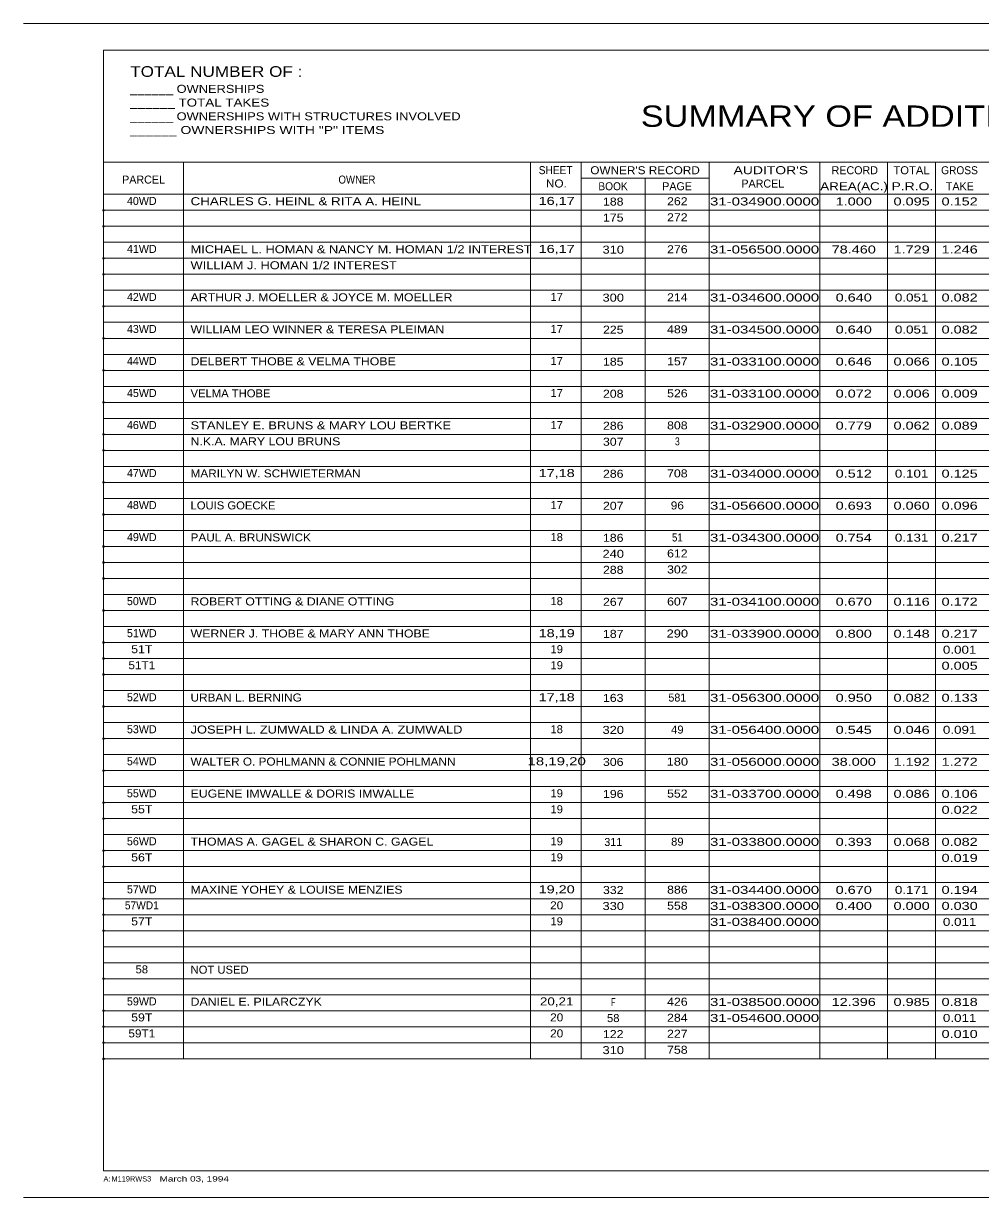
# Model space of a CAD drawing. Extents: x -1 to 34.5, y 0 to 22.
# Drawn here: x -1 to 16.94, y 0 to 22 of the extents above; entities that cross this region are included whole.
import ezdxf
from ezdxf.enums import TextEntityAlignment as Align

# ---------------------------------------------------------------- set-up
doc = ezdxf.new("R2010")
doc.units = 0
doc.header["$LTSCALE"] = 0.06
doc.header["$PDMODE"] = 32
doc.header["$PDSIZE"] = 0.03
doc.layers.add('1', color=7, linetype='Continuous', lineweight=13)

msp = doc.modelspace()

# ---------------------------------------------------------------- linework, layer by layer
at = {"layer": '1'}
for p, q in [((-1, 22), (34.5, 22)), ((0.5, 21.5), (34, 21.5)), ((0.5, 0.5), (0.5, 21.5)), ((0.5, 19.4), (34, 19.4)), ((2, 2.6), (2, 19.4)), ((8.5, 2.6), (8.5, 19.4)), ((9.45025, 2.6), (9.45025, 19.4)), ((11.85025, 2.6), (11.85025, 19.4)), ((13.92625, 2.6), (13.92625, 19.4)), ((15.19617, 2.6), (15.19617, 19.4)), ((16.09617, 2.6), (16.09617, 19.4)), ((9.45025, 19.1), (11.85025, 19.1)), ((10.65025, 2.6), (10.65025, 19.1)), ((0.5, 18.8), (34, 18.8)), ((0.5, 18.5), (34, 18.5)), ((0.5, 18.2), (34, 18.2)), ((0.5, 17.9), (34, 17.9)), ((0.5, 17.6), (34, 17.6)), ((0.5, 17.3), (34, 17.3)), ((0.5, 17), (34, 17)), ((0.5, 16.7), (34, 16.7)), ((0.5, 16.4), (34, 16.4)), ((0.5, 16.1), (34, 16.1)), ((0.5, 15.8), (34, 15.8)), ((0.5, 15.5), (34, 15.5)), ((0.5, 15.2), (34, 15.2)), ((0.5, 14.9), (34, 14.9)), ((0.5, 14.6), (34, 14.6)), ((0.5, 14.3), (34, 14.3)), ((0.5, 14), (34, 14)), ((0.5, 13.7), (34, 13.7)), ((0.5, 13.4), (34, 13.4)), ((0.5, 13.1), (34, 13.1)), ((0.5, 12.8), (34, 12.8)), ((0.5, 12.5), (34, 12.5)), ((0.5, 12.2), (34, 12.2)), ((0.5, 11.9), (34, 11.9)), ((0.5, 11.6), (34, 11.6)), ((0.5, 11.3), (34, 11.3)), ((0.5, 11), (34, 11)), ((0.5, 10.7), (34, 10.7)), ((0.5, 10.4), (34, 10.4)), ((0.5, 10.1), (34, 10.1)), ((0.5, 9.8), (34, 9.8)), ((0.5, 9.5), (34, 9.5)), ((0.5, 9.2), (34, 9.2)), ((0.5, 8.9), (34, 8.9)), ((0.5, 8.6), (34, 8.6)), ((0.5, 8.3), (34, 8.3)), ((0.5, 8), (34, 8)), ((0.5, 7.7), (34, 7.7)), ((0.5, 7.4), (34, 7.4)), ((0.5, 7.1), (34, 7.1)), ((0.5, 6.8), (34, 6.8)), ((0.5, 6.5), (34, 6.5)), ((0.5, 6.2), (34, 6.2)), ((0.5, 5.9), (34, 5.9)), ((0.5, 5.6), (34, 5.6)), ((0.5, 5.3), (34, 5.3)), ((0.5, 5), (34, 5)), ((0.5, 4.7), (34, 4.7)), ((0.5, 4.4), (34, 4.4)), ((0.5, 4.1), (34, 4.1)), ((0.5, 3.8), (34, 3.8)), ((0.5, 3.5), (34, 3.5)), ((0.5, 3.2), (34, 3.2)), ((0.5, 2.9), (34, 2.9)), ((0.5, 2.6), (34, 2.6)), ((0.5, 2.6), (12.5, 2.6)), ((-1, 0), (34.5, 0))]:
    msp.add_line(p, q, dxfattribs=at)
msp.add_lwpolyline([(34, 21.5), (34, 0.5), (0.5, 0.5)], dxfattribs=at)
for p in [(0.5, 18.5), (0.5, 18.2), (0.5, 17.6), (0.5, 17.3), (0.5, 16.7), (0.5, 16.1), (0.5, 15.5), (0.5, 14.9), (0.5, 14.3), (0.5, 14), (0.5, 13.4), (0.5, 12.8), (0.5, 12.2), (0.5, 11.9), (0.5, 11.6), (0.5, 11), (0.5, 10.4), (0.5, 10.1), (0.5, 9.8), (0.5, 9.2), (0.5, 8.6), (0.5, 8), (0.5, 7.4), (0.5, 7.1), (0.5, 6.5), (0.5, 6.2), (0.5, 5.6), (0.5, 5.3), (0.5, 5), (0.5, 4.1), (0.5, 3.5), (0.5, 3.2), (0.5, 2.9), (0.5, 2.6)]:
    msp.add_point(p, dxfattribs=at)

# ---------------------------------------------------------------- texts
for s, height, width, p in [('TOTAL NUMBER OF :', 0.2, 1.2, (1, 21)), ('______ OWNERSHIPS', 0.15, 1.2, (1, 20.7)), ('______ TOTAL TAKES', 0.15, 1.25, (1, 20.44283)), ('______ OWNERSHIPS WITH STRUCTURES INVOLVED', 0.15, 1.2, (1, 20.18575)), ('______ OWNERSHIPS WITH "P" ITEMS', 0.15, 1.3, (1, 19.92858)), ("AUDITOR'S ", 0.15, 1.3, (12.30883, 19.176)), (' NO.', 0.15, 1.1, (8.73083, 18.92683)), ('CHARLES G. HEINL & RITA A. HEINL', 0.15, 1.25, (2.13167, 18.59433)), ('MICHAEL L. HOMAN & NANCY M. HOMAN 1/2 INTEREST', 0.15, 1.2, (2.13167, 17.69433)), ('WILLIAM J. HOMAN 1/2 INTEREST', 0.15, 1.2, (2.13167, 17.39433)), ('ARTHUR J. MOELLER & JOYCE M. MOELLER', 0.15, 1.15, (2.13167, 16.79433)), ('WILLIAM LEO WINNER & TERESA PLEIMAN', 0.15, 1.15, (2.13167, 16.19433)), ('DELBERT THOBE & VELMA THOBE', 0.15, 1.15, (2.13167, 15.59433)), ('VELMA THOBE', 0.15, 1.05, (2.13167, 14.99433)), ('STANLEY E. BRUNS & MARY LOU BERTKE', 0.15, 1.2, (2.13167, 14.39433)), ('N.K.A. MARY LOU BRUNS', 0.15, 1.15, (2.13167, 14.09433)), ('MARILYN W. SCHWIETERMAN', 0.15, 1.1, (2.13167, 13.49433)), ('LOUIS GOECKE', 0.15, 1.05, (2.13167, 12.89433)), ('PAUL A. BRUNSWICK', 0.15, 1.1, (2.13167, 12.29433)), ('ROBERT OTTING & DIANE OTTING', 0.15, 1.15, (2.13167, 11.09433)), ('WERNER J. THOBE & MARY ANN THOBE', 0.15, 1.15, (2.13167, 10.49433)), ('URBAN L. BERNING', 0.15, 1.1, (2.13167, 9.29433)), ('JOSEPH L. ZUMWALD & LINDA A. ZUMWALD', 0.15, 1.2, (2.13167, 8.69433)), ('WALTER O. POHLMANN & CONNIE POHLMANN', 0.15, 1.1, (2.13167, 8.09433)), ('EUGENE IMWALLE & DORIS IMWALLE', 0.15, 1.15, (2.13167, 7.49433)), ('THOMAS A. GAGEL & SHARON C. GAGEL', 0.15, 1.15, (2.13167, 6.59433)), ('MAXINE YOHEY & LOUISE MENZIES', 0.15, 1.15, (2.13167, 5.69433)), ('NOT USED', 0.15, 1.05, (2.13167, 4.19433)), ('DANIEL E. PILARCZYK', 0.15, 1.15, (2.13167, 3.59433)), ('March 03, 1994', 0.1, 1.4, (1.55, 0.3))]:
    msp.add_text(s, height=height, dxfattribs=dict(at, width=width)).set_placement(p)
for s, height, width, p in [('SUMMARY OF ADDITIONAL RIGHT-OF-WAY', 0.4, 1.2, (17.2385, 20.06342)), ('OWNER', 0.15, 0.9, (5.25004, 19)), ('SHEET', 0.15, 0.95, (8.97467, 19.17683)), ("OWNER'S RECORD", 0.15, 1.1, (10.65025, 19.175)), ('TOTAL', 0.15, 1.05, (15.64387, 19.175)), ('GROSS', 0.15, 0.95, (16.54367, 19.175)), ('BOOK', 0.15, 0.95, (10.05029, 18.875)), ('AREA(AC.)', 0.15, 1.25, (14.56738, 18.875)), ('P.R.O.', 0.15, 1.3, (15.66092, 18.875)), ('16,17', 0.15, 1.35, (8.99346, 18.60025)), ('188', 0.15, 1.15, (10.05379, 18.5875)), ('262', 0.15, 1.15, (11.25512, 18.59383)), ('31-034900.0000', 0.15, 1.4, (12.89025, 18.59)), ('1.000', 0.15, 1.35, (14.56129, 18.59)), ('0.095', 0.15, 1.35, (15.64612, 18.59)), ('0.152', 0.15, 1.35, (16.54612, 18.59)), ('175', 0.15, 1.15, (10.05379, 18.2875)), ('272', 0.15, 1.15, (11.25512, 18.29383)), ('16,17', 0.15, 1.35, (8.99346, 17.70025)), ('310', 0.15, 1.2, (10.05387, 17.6875)), ('276', 0.15, 1.15, (11.25521, 17.69383)), ('31-056500.0000', 0.15, 1.4, (12.89025, 17.69)), ('78.460', 0.15, 1.35, (14.56121, 17.69)), ('1.729', 0.15, 1.35, (15.64612, 17.69)), ('1.246', 0.15, 1.35, (16.54621, 17.69)), ('17', 0.15, 1.05, (8.9935, 16.80025)), ('214', 0.15, 1.15, (11.25512, 16.79383)), ('31-034600.0000', 0.15, 1.4, (12.89025, 16.79)), ('0.640', 0.15, 1.35, (14.56129, 16.79)), ('0.051', 0.15, 1.25, (15.64617, 16.79)), ('0.082', 0.15, 1.35, (16.54612, 16.79)), ('300', 0.15, 1.2, (10.05387, 16.7875)), ('17', 0.15, 1.05, (8.9935, 16.20025)), ('225', 0.15, 1.15, (10.05379, 16.1875)), ('489', 0.15, 1.15, (11.25512, 16.19383)), ('31-034500.0000', 0.15, 1.4, (12.89025, 16.19)), ('0.640', 0.15, 1.35, (14.56129, 16.19)), ('0.051', 0.15, 1.25, (15.64617, 16.19)), ('0.082', 0.15, 1.35, (16.54612, 16.19)), ('17', 0.15, 1.05, (8.9935, 15.60025)), ('185', 0.15, 1.15, (10.05379, 15.5875)), ('157', 0.15, 1.15, (11.25512, 15.59383)), ('31-033100.0000', 0.15, 1.4, (12.89025, 15.59)), ('0.646', 0.15, 1.35, (14.56129, 15.59)), ('0.066', 0.15, 1.35, (15.64621, 15.59)), ('0.105', 0.15, 1.35, (16.54612, 15.59)), ('17', 0.15, 1.05, (8.9935, 15.00025)), ('208', 0.15, 1.15, (10.05379, 14.9875)), ('526', 0.15, 1.15, (11.25521, 14.99383)), ('31-033100.0000', 0.15, 1.4, (12.89025, 14.99)), ('0.072', 0.15, 1.35, (14.56121, 14.99)), ('0.006', 0.15, 1.35, (15.64621, 14.99)), ('0.009', 0.15, 1.35, (16.54612, 14.99)), ('17', 0.15, 1.05, (8.9935, 14.40025)), ('286', 0.15, 1.15, (10.05387, 14.3875)), ('808', 0.15, 1.15, (11.25512, 14.39383)), ('31-032900.0000', 0.15, 1.4, (12.89025, 14.39)), ('0.779', 0.15, 1.35, (14.56121, 14.39)), ('0.062', 0.15, 1.35, (15.64612, 14.39)), ('0.089', 0.15, 1.35, (16.54612, 14.39)), ('307', 0.15, 1.15, (10.05379, 14.0875)), ('3', 0.15, 0.8, (11.25517, 14.09383)), ('17,18', 0.15, 1.35, (8.99346, 13.50025)), ('708', 0.15, 1.15, (11.25512, 13.49383)), ('31-034000.0000', 0.15, 1.4, (12.89025, 13.49)), ('0.512', 0.15, 1.35, (14.56121, 13.49)), ('0.101', 0.15, 1.25, (15.64617, 13.49)), ('0.125', 0.15, 1.35, (16.54612, 13.49)), ('286', 0.15, 1.15, (10.05387, 13.4875)), ('17', 0.15, 1.05, (8.9935, 12.90025)), ('207', 0.15, 1.15, (10.05379, 12.8875)), ('96', 0.15, 1.1, (11.25517, 12.89383)), ('31-056600.0000', 0.15, 1.4, (12.89025, 12.89)), ('0.693', 0.15, 1.35, (14.56121, 12.89)), ('0.060', 0.15, 1.35, (15.64621, 12.89)), ('0.096', 0.15, 1.35, (16.54621, 12.89)), ('18', 0.15, 1.05, (8.9935, 12.30025)), ('186', 0.15, 1.15, (10.05387, 12.2875)), ('51', 0.15, 0.9, (11.25521, 12.29383)), ('31-034300.0000', 0.15, 1.4, (12.89025, 12.29)), ('0.754', 0.15, 1.35, (14.56121, 12.29)), ('0.131', 0.15, 1.25, (15.64617, 12.29)), ('0.217', 0.15, 1.35, (16.54612, 12.29)), ('240', 0.15, 1.2, (10.05387, 11.9875)), ('612', 0.15, 1.15, (11.25512, 11.99383)), ('288', 0.15, 1.15, (10.05379, 11.6875)), ('302', 0.15, 1.15, (11.25512, 11.69383)), ('18', 0.15, 1.05, (8.9935, 11.10025)), ('267', 0.15, 1.15, (10.05379, 11.0875)), ('607', 0.15, 1.15, (11.25512, 11.09383)), ('31-034100.0000', 0.15, 1.4, (12.89025, 11.09)), ('0.670', 0.15, 1.35, (14.56129, 11.09)), ('0.116', 0.15, 1.35, (15.64621, 11.09)), ('0.172', 0.15, 1.35, (16.54612, 11.09)), ('18,19', 0.15, 1.35, (8.99346, 10.50025)), ('187', 0.15, 1.15, (10.05379, 10.4875)), ('290', 0.15, 1.2, (11.25521, 10.49383)), ('31-033900.0000', 0.15, 1.4, (12.89025, 10.49)), ('0.800', 0.15, 1.35, (14.56129, 10.49)), ('0.148', 0.15, 1.35, (15.64612, 10.49)), ('0.217', 0.15, 1.35, (16.54612, 10.49)), ('51T', 0.15, 1.15, (1.21771, 10.20025)), ('19', 0.15, 1.05, (8.9935, 10.20025)), ('0.001', 0.15, 1.25, (16.54617, 10.19)), ('51T1', 0.15, 1.1, (1.21767, 9.90025)), ('19', 0.15, 1.05, (8.9935, 9.90025)), ('0.005', 0.15, 1.35, (16.54612, 9.89)), ('17,18', 0.15, 1.35, (8.99346, 9.30025)), ('163', 0.15, 1.15, (10.05379, 9.2875)), ('31-056300.0000', 0.15, 1.4, (12.89025, 9.29)), ('0.950', 0.15, 1.35, (14.56129, 9.29)), ('0.082', 0.15, 1.35, (15.64612, 9.29)), ('0.133', 0.15, 1.35, (16.54612, 9.29)), ('18', 0.15, 1.05, (8.9935, 8.70025)), ('320', 0.15, 1.2, (10.05387, 8.6875)), ('49', 0.15, 1.05, (11.25517, 8.69383)), ('31-056400.0000', 0.15, 1.4, (12.89025, 8.69)), ('0.545', 0.15, 1.35, (14.56121, 8.69)), ('0.046', 0.15, 1.35, (15.64621, 8.69)), ('0.091', 0.15, 1.25, (16.54617, 8.69)), ('18,19,20', 0.15, 1.4, (8.99346, 8.10025)), ('306', 0.15, 1.15, (10.05387, 8.0875)), ('180', 0.15, 1.2, (11.25521, 8.09383)), ('31-056000.0000', 0.15, 1.4, (12.89025, 8.09)), ('38.000', 0.15, 1.35, (14.56121, 8.09)), ('1.192', 0.15, 1.35, (15.64612, 8.09)), ('1.272', 0.15, 1.35, (16.54612, 8.09)), ('19', 0.15, 1.05, (8.9935, 7.50025)), ('196', 0.15, 1.15, (10.05387, 7.4875)), ('552', 0.15, 1.15, (11.25512, 7.49383)), ('31-033700.0000', 0.15, 1.4, (12.89025, 7.49)), ('0.498', 0.15, 1.35, (14.56121, 7.49)), ('0.086', 0.15, 1.35, (15.64621, 7.49)), ('0.106', 0.15, 1.35, (16.54621, 7.49)), ('55T', 0.15, 1.15, (1.21771, 7.20025)), ('19', 0.15, 1.05, (8.9935, 7.20025)), ('0.022', 0.15, 1.35, (16.54612, 7.19)), ('19', 0.15, 1.05, (8.9935, 6.60025)), ('89', 0.15, 1.05, (11.25517, 6.59383)), ('31-033800.0000', 0.15, 1.4, (12.89025, 6.59)), ('0.393', 0.15, 1.35, (14.56121, 6.59)), ('0.068', 0.15, 1.35, (15.64612, 6.59)), ('0.082', 0.15, 1.35, (16.54612, 6.59)), ('56T', 0.15, 1.15, (1.21771, 6.30025)), ('19', 0.15, 1.05, (8.9935, 6.30025)), ('0.019', 0.15, 1.35, (16.54612, 6.29)), ('19,20', 0.15, 1.35, (8.99354, 5.70025)), ('332', 0.15, 1.15, (10.05379, 5.6875)), ('886', 0.15, 1.15, (11.25521, 5.69383)), ('31-034400.0000', 0.15, 1.4, (12.89025, 5.69)), ('0.670', 0.15, 1.35, (14.56129, 5.69)), ('0.171', 0.15, 1.25, (15.64617, 5.69)), ('0.194', 0.15, 1.35, (16.54612, 5.69)), ('57WD1', 0.15, 0.95, (1.21767, 5.40025)), ('20', 0.15, 1.1, (8.9935, 5.40025)), ('330', 0.15, 1.2, (10.05387, 5.3875)), ('558', 0.15, 1.15, (11.25512, 5.39383)), ('31-038300.0000', 0.15, 1.4, (12.89025, 5.39)), ('0.400', 0.15, 1.35, (14.56129, 5.39)), ('0.000', 0.15, 1.35, (15.64621, 5.39)), ('0.030', 0.15, 1.35, (16.54621, 5.39)), ('57T', 0.15, 1.15, (1.21771, 5.10025)), ('19', 0.15, 1.05, (8.9935, 5.10025)), ('31-038400.0000', 0.15, 1.4, (12.89025, 5.09)), ('0.011', 0.15, 1.25, (16.54617, 5.09)), ('58', 0.15, 1.05, (1.21767, 4.20025)), ('20,21', 0.15, 1.25, (8.9935, 3.60025)), ('426', 0.15, 1.15, (11.25521, 3.59383)), ('31-038500.0000', 0.15, 1.4, (12.89025, 3.59)), ('12.396', 0.15, 1.35, (14.56121, 3.59)), ('0.985', 0.15, 1.35, (15.64612, 3.59)), ('0.818', 0.15, 1.35, (16.54612, 3.59)), ('F', 0.15, 0.7, (10.05383, 3.5875)), ('59T', 0.15, 1.15, (1.21771, 3.30025)), ('20', 0.15, 1.1, (8.9935, 3.30025)), ('58', 0.15, 1.05, (10.05383, 3.2875)), ('284', 0.15, 1.15, (11.25512, 3.29383)), ('31-054600.0000', 0.15, 1.4, (12.89025, 3.29)), ('0.011', 0.15, 1.25, (16.54617, 3.29)), ('59T1', 0.15, 1.1, (1.21767, 3.00025)), ('20', 0.15, 1.1, (8.9935, 3.00025)), ('122', 0.15, 1.15, (10.05379, 2.9875)), ('227', 0.15, 1.15, (11.25512, 2.99383)), ('0.010', 0.15, 1.35, (16.54621, 2.99)), ('310', 0.15, 1.2, (10.05387, 2.6875)), ('758', 0.15, 1.15, (11.25512, 2.69383))]:
    msp.add_text(s, height=height, dxfattribs=dict(at, width=width)).set_placement(p, align=Align.CENTER)
for s, p in [('PARCEL', (1.25004, 19)), ('RECORD', (14.58121, 19.175)), ('PAGE', (11.25025, 18.875)), ('TAKE', (16.55008, 18.875)), ('40WD', (1.21762, 18.60025)), ('41WD', (1.21762, 17.70025)), ('42WD', (1.21762, 16.80025)), ('43WD', (1.21762, 16.20025)), ('44WD', (1.21762, 15.60025)), ('45WD', (1.21762, 15.00025)), ('46WD', (1.21762, 14.40025)), ('47WD', (1.21762, 13.50025)), ('48WD', (1.21762, 12.90025)), ('49WD', (1.21762, 12.30025)), ('50WD', (1.21762, 11.10025)), ('51WD', (1.21762, 10.50025)), ('52WD', (1.21762, 9.30025)), ('581', (11.25517, 9.29383)), ('53WD', (1.21762, 8.70025)), ('54WD', (1.21762, 8.10025)), ('55WD', (1.21762, 7.50025)), ('56WD', (1.21762, 6.60025)), ('311', (10.05383, 6.5875)), ('57WD', (1.21762, 5.70025)), ('59WD', (1.21762, 3.60025))]:
    msp.add_text(s, height=0.15, dxfattribs=at).set_placement(p, align=Align.CENTER)
for s, height, p in [('PARCEL', 0.15, (12.45575, 18.926)), ('A:', 0.1, (0.5, 0.3)), ('M119RWS3', 0.1, (0.65, 0.3))]:
    msp.add_text(s, height=height, dxfattribs=at).set_placement(p)

doc.saveas('drawing.dxf')
